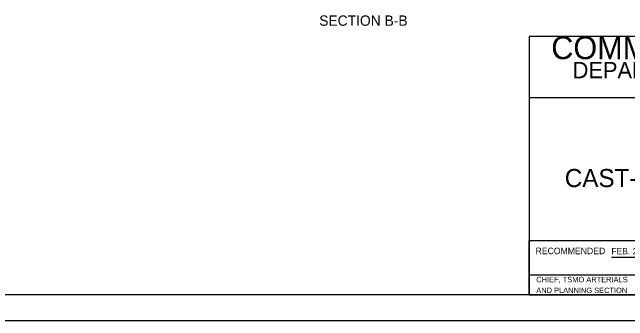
# Model space of a CAD drawing. Extents: x 1299104.8 to 1299141.6, y 239639.8 to 239661.8.
# Drawn here: x 1299120.31 to 1299132.2, y 239639.8 to 239645.76 of the extents above; entities that cross this region are included whole.
import ezdxf

# ---------------------------------------------------------------- set-up
doc = ezdxf.new("R2010")
doc.units = 0
for name, color, linetype in [('1', 7, 'Continuous'), ('DIM TXT', 7, 'Continuous'), ('GS_noplot_1', 7, 'Continuous'), ('GS_plotshape_p', 7, 'Continuous'), ('Level 1', 7, 'Continuous'), ('PTEXT', 7, 'Continuous')]:
    doc.layers.add(name, color=color, linetype=linetype)

msp = doc.modelspace()

# ---------------------------------------------------------------- linework, layer by layer
at = {"layer": '1'}
for p, q in [((1299131.894, 239641.03), (1299133.284, 239641.03)), ((1299130.302, 239640.69), (1299133.427, 239640.69))]:
    msp.add_line(p, q, dxfattribs=at)
at = {"layer": 'GS_noplot_1'}
msp.add_lwpolyline([(1299130.302, 239641.349), (1299136.552, 239641.349), (1299136.552, 239640.301), (1299130.302, 239640.301)], close=True, dxfattribs=at)
at = {"layer": 'GS_plotshape_p'}
msp.add_lwpolyline([(1299104.802, 239661.801), (1299138.802, 239661.801), (1299138.802, 239639.801), (1299104.802, 239639.801)], close=True, dxfattribs=at)
at = {"layer": 'Level 1'}
msp.add_line((1299130.302, 239641.349), (1299138.302, 239641.349), dxfattribs=at)
for points in [[(1299138.302, 239640.301), (1299106.302, 239640.301), (1299106.302, 239661.301), (1299138.302, 239661.301)], [(1299138.302, 239645.294), (1299130.302, 239645.294), (1299130.302, 239644.114), (1299138.302, 239644.114)], [(1299138.302, 239645.294), (1299130.302, 239645.294), (1299130.302, 239640.301), (1299138.302, 239640.301)]]:
    msp.add_lwpolyline(points, close=True, dxfattribs=at)

# ---------------------------------------------------------------- texts
at = {"layer": '1'}
for s, height, p in [('COMMONWEALTH OF PENNSYLVANIA', 0.44223, (1299130.728, 239644.853)), ('DEPARTMENT OF TRANSPORTATION', 0.31514, (1299131.141, 239644.484)), ('RECOMMENDED', 0.125, (1299130.424, 239641.086)), ('FEB. 20, 2024', 0.12303, (1299131.889, 239641.082)), ('CHIEF, TSMO ARTERIALS ', 0.10417, (1299130.438, 239640.544)), ('AND PLANNING SECTION', 0.10417, (1299130.438, 239640.335))]:
    msp.add_text(s, height=height, dxfattribs=at).set_placement(p)
at = {"layer": 'DIM TXT'}
msp.add_text('SECTION B-B', height=0.2, dxfattribs=at).set_placement((1299126.241, 239645.498))
at = {"layer": 'PTEXT'}
msp.add_text('CAST-IN-PLACE OR PRECAST', height=0.35, dxfattribs=at).set_placement((1299130.989, 239642.382))

doc.saveas('drawing.dxf')
